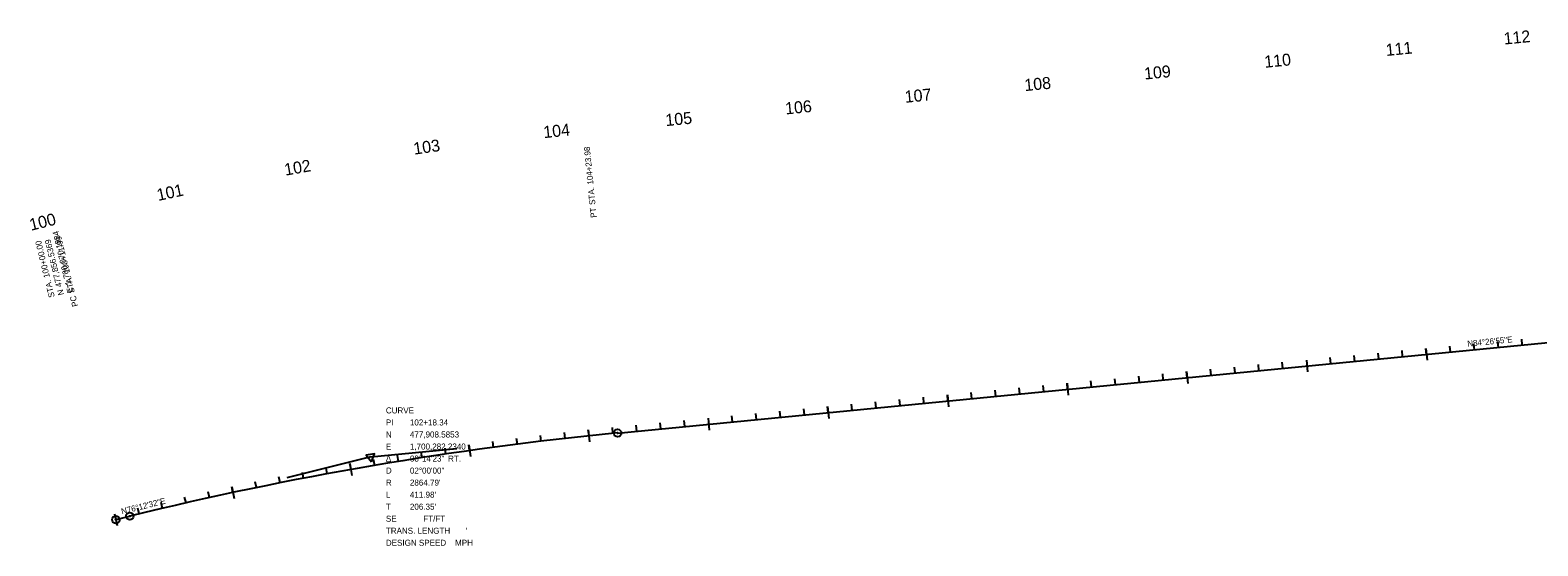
# Model space of a CAD drawing. Extents: x 1699999 to 1705087, y 475568 to 482652.
# Drawn here: x 1699999 to 1701253, y 477835 to 478263 of the extents above; entities that cross this region are included whole.
import ezdxf

# ---------------------------------------------------------------- set-up
doc = ezdxf.new("R2010")
doc.units = 0
for name, color, linetype in [('Default', 7, 'Continuous'), ('DES - DTM - Boundary', 7, 'Continuous'), ('DES - DTM - Ground', 7, 'Continuous'), ('DES - DTM - Points - High', 7, 'Continuous'), ('DESIGN - TYPICAL - Guardrail', 7, 'Continuous'), ('TC_Aggregate', 7, 'Continuous')]:
    doc.layers.add(name, color=color, linetype=linetype)

msp = doc.modelspace()

# ---------------------------------------------------------------- linework, layer by layer
at = {"layer": 'Default'}
for p, q in [((1700487.6, 477928.5), (1701902.1, 478066)), ((1700070.2, 477856.5), (1700081.8, 477859.4))]:
    msp.add_line(p, q, dxfattribs=at)
msp.add_arc((1700764.8, 475077.2), 2864.8, 95.5514, 103.7911, dxfattribs=at)
at = {"layer": 'DES - DTM - Ground'}
for p, q in [((1700487.6, 477928.5), (1701902.1, 478066)), ((1700070.2, 477856.5), (1700081.8, 477859.4))]:
    msp.add_line(p, q, dxfattribs=at)
msp.add_arc((1700764.8, 475077.2), 2864.8, 95.5514, 103.7911, dxfattribs=at)
at = {"layer": 'DES - DTM - Points - High'}
for p, q in [((1701120.7, 477990.1), (1701120.2, 477995)), ((1701140.6, 477992), (1701140.1, 477997)), ((1701160, 477998.9), (1701161, 477989)), ((1701180.4, 477995.9), (1701179.9, 478000.8)), ((1701200.3, 477997.8), (1701199.8, 478002.8)), ((1701220.2, 477999.7), (1701219.7, 478004.7)), ((1701240.1, 478001.7), (1701239.6, 478006.6)), ((1701001.2, 477978.5), (1701000.7, 477983.4)), ((1701021.1, 477980.4), (1701020.6, 477985.4)), ((1701041, 477982.3), (1701040.5, 477987.3)), ((1701060.5, 477989.2), (1701061.4, 477979.3)), ((1701080.8, 477986.2), (1701080.4, 477991.2)), ((1701100.7, 477988.1), (1701100.3, 477993.1)), ((1700861.4, 477969.9), (1700862.4, 477959.9)), ((1700881.8, 477966.9), (1700881.3, 477971.8)), ((1700901.7, 477968.8), (1700901.2, 477973.7)), ((1700921.6, 477970.7), (1700921.1, 477975.7)), ((1700941.5, 477972.7), (1700941, 477977.6)), ((1700960.9, 477979.6), (1700961.9, 477969.6)), ((1700981.3, 477976.5), (1700980.8, 477981.5)), ((1700742.4, 477953.3), (1700742, 477958.3)), ((1700761.9, 477960.2), (1700762.8, 477950.3)), ((1700782.2, 477957.2), (1700781.8, 477962.1)), ((1700802.2, 477959.1), (1700801.7, 477964.1)), ((1700822.1, 477961.1), (1700821.6, 477966)), ((1700842, 477963), (1700841.5, 477967.9)), ((1700603.1, 477939.8), (1700602.6, 477944.7)), ((1700623, 477941.7), (1700622.5, 477946.7)), ((1700642.9, 477943.6), (1700642.4, 477948.6)), ((1700662.3, 477950.6), (1700663.3, 477940.6)), ((1700682.7, 477947.5), (1700682.2, 477952.5)), ((1700702.6, 477949.4), (1700702.1, 477954.4)), ((1700722.5, 477951.4), (1700722, 477956.3)), ((1700483.7, 477928.2), (1700483.2, 477933.1)), ((1700503.6, 477930.1), (1700503.1, 477935.1)), ((1700523.5, 477932), (1700523, 477937)), ((1700543.4, 477934), (1700542.9, 477938.9)), ((1700562.8, 477940.9), (1700563.8, 477930.9)), ((1700583.2, 477937.8), (1700582.7, 477942.8)), ((1700384.3, 477916.6), (1700383.7, 477921.5)), ((1700404.2, 477919.2), (1700403.5, 477924.1)), ((1700424, 477921.6), (1700423.4, 477926.6)), ((1700443.9, 477924), (1700443.3, 477928.9)), ((1700463.2, 477931.1), (1700464.3, 477921.2)), ((1700305.2, 477904.9), (1700304.4, 477909.8)), ((1700324.9, 477908), (1700324.2, 477912.9)), ((1700344.7, 477911), (1700344, 477916)), ((1700363.8, 477918.8), (1700365.2, 477908.9)), ((1700226.4, 477891), (1700225.5, 477895.8)), ((1700246.1, 477894.6), (1700245.2, 477899.5)), ((1700264.9, 477903.1), (1700266.6, 477893.3)), ((1700285.5, 477901.6), (1700284.6, 477906.5)), ((1700166.6, 477883.9), (1700168.7, 477874.2)), ((1700187.2, 477883.2), (1700186.2, 477888)), ((1700206.8, 477887.1), (1700205.8, 477892)), ((1700109.1, 477865.9), (1700107.9, 477870.8)), ((1700128.6, 477870.4), (1700127.4, 477875.3)), ((1700148.1, 477874.8), (1700147, 477879.7)), ((1700069, 477861.4), (1700071.4, 477851.7)), ((1700089.6, 477861.3), (1700088.4, 477866.1))]:
    msp.add_line(p, q, dxfattribs=at)
at = {"layer": 'DESIGN - TYPICAL - Guardrail'}
for p, q in [((1701160.5, 477993.9), (1701160, 477998.9)), ((1701060.5, 477989.2), (1701061.4, 477979.3)), ((1700861.9, 477964.9), (1700861.4, 477969.9)), ((1700961.4, 477974.6), (1700960.9, 477979.6)), ((1700762.3, 477955.2), (1700761.9, 477960.2)), ((1700662.8, 477945.6), (1700662.3, 477950.5)), ((1700562.8, 477940.9), (1700563.8, 477930.9)), ((1700463.8, 477926.1), (1700463.2, 477931.1)), ((1700364.5, 477913.9), (1700363.8, 477918.8)), ((1700265.8, 477898.2), (1700264.9, 477903.1)), ((1700167.6, 477879.1), (1700166.6, 477883.9)), ((1700069, 477861.4), (1700071.4, 477851.7))]:
    msp.add_line(p, q, dxfattribs=at)
for centre, radius in [((1700487.6, 477928.5), 3.14), ((1700487.6, 477928.5), 0.33), ((1700070.2, 477856.5), 3.14), ((1700070.2, 477856.5), 0.33), ((1700081.8, 477859.4), 3.14), ((1700081.8, 477859.4), 0.33)]:
    msp.add_circle(centre, radius, dxfattribs=at)
at = {"layer": 'TC_Aggregate'}
for q in [(1700212.3, 477891.4), (1700353.9, 477915.6), (1700282.2, 477908.6)]:
    msp.add_line((1700282.2, 477908.6), q, dxfattribs=at)
msp.add_lwpolyline([(1700282.9, 477904.5), (1700285.4, 477911.2), (1700278.3, 477910)], close=True, dxfattribs=at)

# ---------------------------------------------------------------- texts
at = {"layer": 'DES - DTM - Boundary'}
for s, rotation, p in [('104+23.98', 95.5514, (1700467.5, 478135.3)), (' STA. ', 95.5514, (1700469.3, 478116.6)), ('PT', 95.5514, (1700470.2, 478107.7)), ('100+11.99', 103.7911, (1700032.1, 478061.9)), (' STA. ', 103.7911, (1700036.6, 478043.6)), ('PC', 103.7911, (1700038.9, 478034.2))]:
    msp.add_text(s, height=4.98, rotation=rotation, dxfattribs=at).set_placement(p)
for s, p in [('CURVE    ', (1700294.8, 477944.8)), ('PI', (1700294.8, 477934.8)), ('102+18.34', (1700314.8, 477934.8)), ('N', (1700294.8, 477924.8)), ('E', (1700294.8, 477914.8)), ('477,908.5853', (1700314.8, 477924.8)), ('1,700,282.2340', (1700314.8, 477914.8)), ('Δ', (1700294.8, 477904.8)), ('08°14\'23"', (1700314.8, 477904.8)), (' RT.', (1700344.7, 477904.8)), ('D', (1700294.8, 477894.8)), ('02°00\'00"', (1700314.8, 477894.8)), ('R', (1700294.8, 477884.8)), ("2864.79'", (1700314.8, 477884.8)), ('T', (1700294.8, 477864.8)), ('L', (1700294.8, 477874.8)), ("411.98'", (1700314.8, 477874.8)), ("206.35'", (1700314.8, 477864.8)), ('SE', (1700294.8, 477854.8)), ('      FT/FT', (1700314.8, 477854.8)), ("TRANS. LENGTH       '", (1700294.8, 477844.8)), ('DESIGN SPEED    MPH', (1700294.8, 477834.8))]:
    msp.add_text(s, height=5, dxfattribs=at).set_placement(p)
at = {"layer": 'DES - DTM - Points - High'}
for s, rotation, p in [('112', 5.5514, (1701225.1, 478251.4)), ('111', 5.5514, (1701127, 478241.9)), ('109', 5.5514, (1700926, 478222.3)), ('110', 5.5514, (1701026, 478232.1)), ('108', 5.5514, (1700826.4, 478212.7)), ('107', 5.5514, (1700726.9, 478203)), ('105', 5.5514, (1700527.8, 478183.6)), ('106', 5.5514, (1700627.4, 478193.3)), ('104', 6.0309, (1700426.3, 478173.6)), ('103', 8.0309, (1700318.4, 478159.9)), ('102', 10.0309, (1700211.2, 478142.4)), ('101', 12.0309, (1700105.4, 478121.4)), ('100', 13.7911, (1699999.6, 478096.6))]:
    msp.add_text(s, height=9.96, rotation=rotation, dxfattribs=at).set_placement(p)
at = {"layer": 'DESIGN - TYPICAL - Guardrail'}
for s, rotation, p in [('110', 5.5514, (1701026, 478232.1)), ('105', 5.5514, (1700527.8, 478183.6)), ('100', 13.7911, (1699999.6, 478096.6))]:
    msp.add_text(s, height=9.96, rotation=rotation, dxfattribs=at).set_placement(p)
at = {"layer": 'TC_Aggregate'}
for s, rotation, p in [('1,700,070.1884', 103.7911, (1700033.3, 478052)), ('100+00.00', 103.7911, (1700015.4, 478058.2)), ('477,856.5369', 103.7911, (1700025.5, 478050.4)), ('STA. ', 103.7911, (1700019.4, 478041.8)), ('N ', 103.7911, (1700027.2, 478043.7)), ('E ', 103.7911, (1700034.9, 478045.6)), ('N84°26\'55"E', 5.5514, (1701194.6, 478000.3)), ('N76°12\'32"E', 13.7911, (1700075.3, 477860.9))]:
    msp.add_text(s, height=4.98, rotation=rotation, dxfattribs=at).set_placement(p)

doc.saveas('drawing.dxf')
